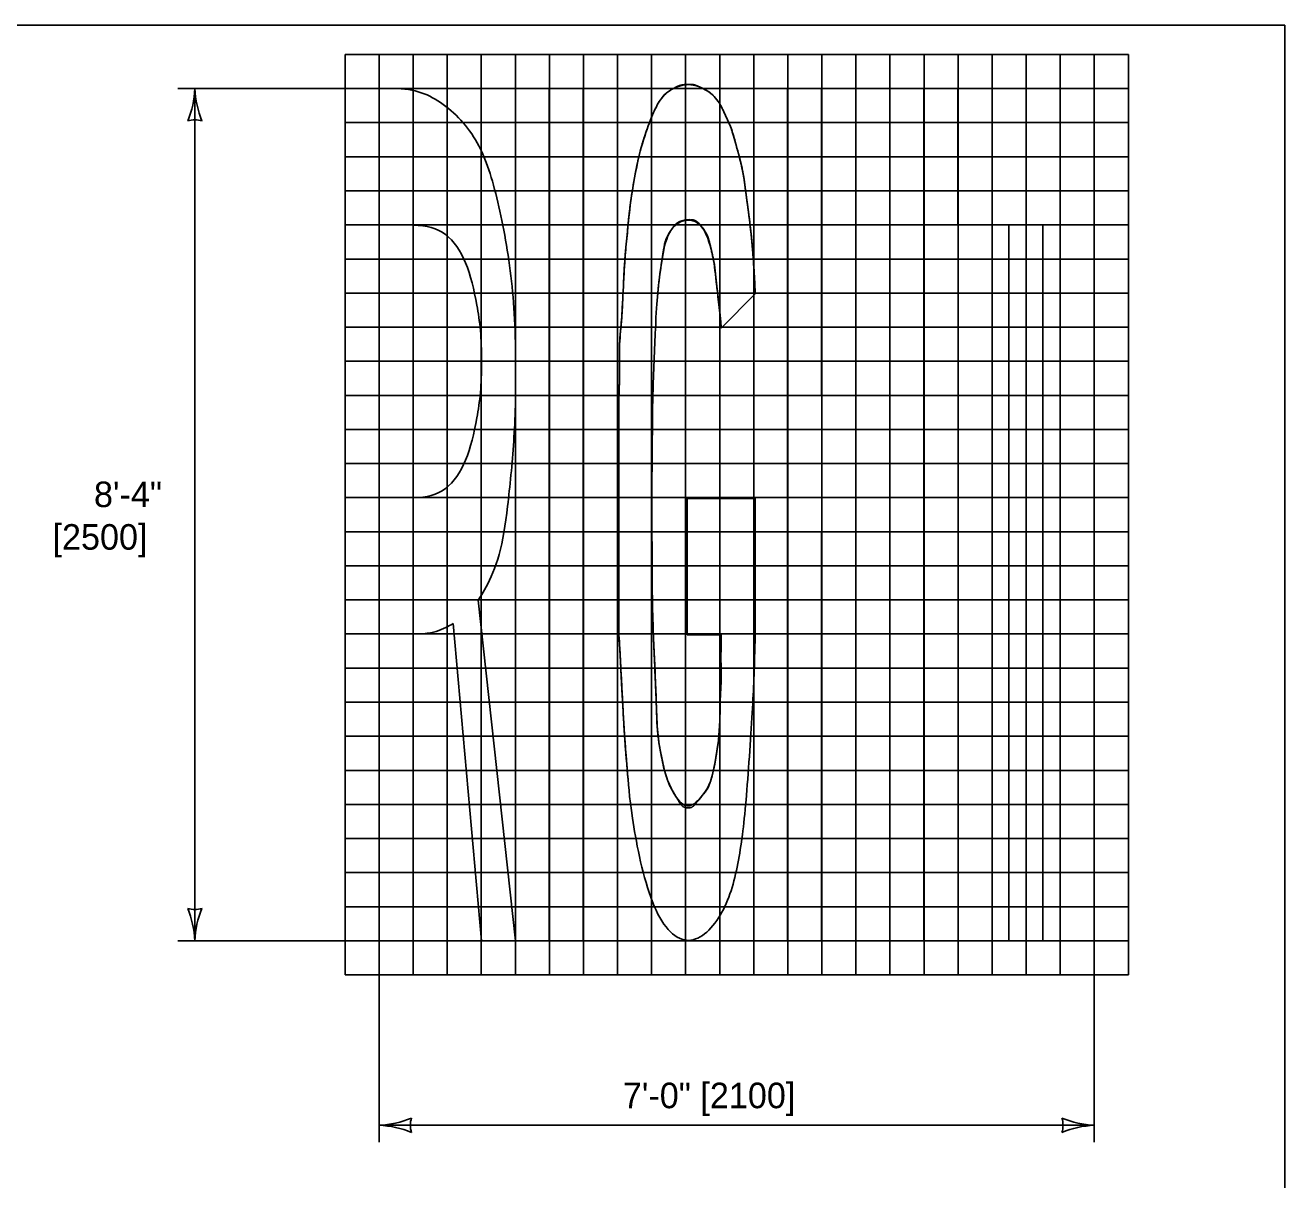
# Model space of a CAD drawing. Extents: x 49991.4 to 50021, y 49987.6 to 50011.4.
# Drawn here: x 50005.656 to 50008.615, y 50008.552 to 50011.263 of the extents above; entities that cross this region are included whole.
import ezdxf

# ---------------------------------------------------------------- set-up
doc = ezdxf.new("R2010")
doc.units = 0
for name, color, linetype in [('Level 1', 7, 'Continuous'), ('Level 2', 7, 'Continuous'), ('Level 3', 7, 'Continuous'), ('Level 9', 7, 'Continuous')]:
    doc.layers.add(name, color=color, linetype=linetype)

msp = doc.modelspace()

# ---------------------------------------------------------------- linework, layer by layer
at = {"layer": 'Level 1'}
for p, q in [((50006.4876, 50009.1134), (50006.4876, 50011.1132)), ((50006.4876, 50009.1134), (50006.4876, 50011.1132)), ((50006.4876, 50009.1134), (50006.4876, 50011.1132)), ((50006.9669, 50011.1142), (50006.887, 50011.1142)), ((50006.887, 50011.1142), (50006.887, 50009.1133)), ((50006.9669, 50009.1133), (50006.9669, 50011.1142)), ((50007.5267, 50011.1142), (50007.4468, 50011.1142)), ((50007.4468, 50011.1142), (50007.4468, 50009.1133)), ((50007.5267, 50011.1142), (50007.4468, 50011.1142)), ((50007.4468, 50011.1142), (50007.4468, 50009.1133)), ((50007.5267, 50010.3938), (50007.5267, 50011.1142)), ((50007.5267, 50010.3938), (50007.5267, 50011.1142)), ((50007.7668, 50011.1142), (50007.6868, 50011.1142)), ((50007.6868, 50011.1142), (50007.6868, 50010.3938)), ((50007.7668, 50011.1142), (50007.6868, 50011.1142)), ((50007.6868, 50011.1142), (50007.6868, 50010.3938)), ((50007.7668, 50009.1133), (50007.7668, 50011.1142)), ((50007.7668, 50009.1133), (50007.7668, 50011.1142)), ((50008.1667, 50011.1142), (50007.8467, 50011.1142)), ((50007.8467, 50011.1142), (50007.8467, 50010.7939)), ((50008.1667, 50010.7939), (50008.1667, 50011.1142)), ((50006.5676, 50010.1533), (50006.5676, 50010.7932)), ((50006.5676, 50010.7932), (50006.5676, 50010.1533)), ((50006.5676, 50010.7932), (50006.5676, 50010.1533)), ((50007.8467, 50010.7939), (50007.9667, 50010.7939)), ((50007.9667, 50010.7939), (50007.9667, 50009.1133)), ((50008.0467, 50009.1133), (50008.0467, 50010.7939)), ((50008.0467, 50010.7939), (50008.1667, 50010.7939)), ((50007.291, 50010.5518), (50007.371, 50010.6318)), ((50007.291, 50010.5518), (50007.371, 50010.6318)), ((50007.0509, 50010.3917), (50007.0509, 50009.8316)), ((50007.0509, 50010.3917), (50007.0509, 50009.8316)), ((50007.6868, 50010.3938), (50007.5267, 50010.3938)), ((50007.6868, 50010.3938), (50007.5267, 50010.3938)), ((50007.2109, 50010.1517), (50007.371, 50010.1517)), ((50007.2109, 50010.1517), (50007.2109, 50009.8316)), ((50007.371, 50010.1517), (50007.2109, 50010.1517)), ((50007.2109, 50010.1517), (50007.2109, 50009.8316)), ((50007.371, 50010.1517), (50007.371, 50009.8316)), ((50007.371, 50009.8316), (50007.371, 50010.1517)), ((50007.5267, 50009.1133), (50007.5267, 50010.0738)), ((50007.5267, 50009.1133), (50007.5267, 50010.0738)), ((50007.5273, 50010.0737), (50007.6867, 50010.0737)), ((50007.5274, 50010.0738), (50007.6874, 50010.0738)), ((50007.6868, 50010.0738), (50007.6868, 50009.1133)), ((50007.6868, 50010.0738), (50007.6868, 50009.1133)), ((50006.7202, 50009.9133), (50006.8077, 50009.1134)), ((50006.7202, 50009.9133), (50006.8077, 50009.1134)), ((50006.7202, 50009.9133), (50006.8077, 50009.1134)), ((50006.7277, 50009.1134), (50006.6618, 50009.8584)), ((50006.7277, 50009.1134), (50006.6618, 50009.8584)), ((50006.7277, 50009.1134), (50006.6618, 50009.8584)), ((50006.5676, 50009.8333), (50006.5676, 50009.1134)), ((50006.5676, 50009.8333), (50006.5676, 50009.1134)), ((50006.5676, 50009.8333), (50006.5676, 50009.1134)), ((50007.2109, 50009.8316), (50007.291, 50009.8316)), ((50007.2109, 50009.8316), (50007.291, 50009.8316)), ((50006.5676, 50009.1134), (50006.4876, 50009.1134)), ((50006.5676, 50009.1134), (50006.4876, 50009.1134)), ((50006.5676, 50009.1134), (50006.4876, 50009.1134)), ((50006.8077, 50009.1134), (50006.7277, 50009.1134)), ((50006.8077, 50009.1134), (50006.7277, 50009.1134)), ((50006.8077, 50009.1134), (50006.7277, 50009.1134)), ((50006.887, 50009.1133), (50006.9669, 50009.1133)), ((50007.4468, 50009.1133), (50007.5267, 50009.1133)), ((50007.4468, 50009.1133), (50007.5267, 50009.1133)), ((50007.6868, 50009.1133), (50007.7668, 50009.1133)), ((50007.6868, 50009.1133), (50007.7668, 50009.1133)), ((50007.9667, 50009.1133), (50008.0467, 50009.1133))]:
    msp.add_line(p, q, dxfattribs=at)
msp.add_lwpolyline([(50008.6146, 50011.2628), (50000.3356, 50011.2628), (50000.3356, 50000.0624), (50008.6146, 50000.0624)], close=True, dxfattribs=at)
for points, degree in [([(50006.4876, 50011.1132), (50006.5505, 50011.1179), (50006.6207, 50011.1), (50006.7184, 50011.007), (50006.7627, 50010.8775), (50006.7992, 50010.6887), (50006.8086, 50010.5541), (50006.8077, 50010.4733)], 3), ([(50006.4876, 50011.1132), (50006.5505, 50011.1179), (50006.6207, 50011.1), (50006.7184, 50011.007), (50006.7627, 50010.8775), (50006.7992, 50010.6887), (50006.8086, 50010.5541), (50006.8077, 50010.4733)], 3), ([(50006.4876, 50011.1132), (50006.5505, 50011.1179), (50006.6207, 50011.1), (50006.7184, 50011.007), (50006.7627, 50010.8775), (50006.7992, 50010.6887), (50006.8086, 50010.5541), (50006.8077, 50010.4733)], 3), ([(50007.0509, 50010.3917), (50007.0516, 50010.4147), (50007.0529, 50010.4527), (50007.051, 50010.5134), (50007.0579, 50010.5737), (50007.0609, 50010.6473), (50007.0654, 50010.7285), (50007.0703, 50010.7702), (50007.0765, 50010.8407), (50007.0866, 50010.9025), (50007.1014, 50010.9763), (50007.1269, 50011.0469), (50007.142, 50011.08), (50007.1645, 50011.11), (50007.2106, 50011.1281), (50007.2501, 50011.116), (50007.2839, 50011.0901), (50007.3005, 50011.0511), (50007.3147, 50011.0229), (50007.3251, 50010.9839), (50007.3417, 50010.9253), (50007.3476, 50010.8779), (50007.3575, 50010.8075), (50007.3649, 50010.7392), (50007.3686, 50010.6785), (50007.3704, 50010.6439), (50007.371, 50010.6318)], 3), ([(50007.1741, 50011.1116), (50007.1585, 50011.1021), (50007.1496, 50011.0901), (50007.1425, 50011.0782)], 2), ([(50007.2112, 50011.1238), (50007.1981, 50011.1232), (50007.1846, 50011.1179), (50007.1741, 50011.1116)], 2), ([(50007.2459, 50011.1154), (50007.2351, 50011.1206), (50007.2233, 50011.1243), (50007.2112, 50011.1238)], 2), ([(50007.2805, 50011.0881), (50007.2715, 50011.0996), (50007.2595, 50011.1088), (50007.2459, 50011.1154)], 2), ([(50007.3018, 50011.0493), (50007.2959, 50011.0619), (50007.2898, 50011.0762), (50007.2805, 50011.0881)], 2), ([(50007.1425, 50011.0782), (50007.1365, 50011.0681), (50007.1319, 50011.0579), (50007.1259, 50011.0427)], 2), ([(50007.1259, 50011.0427), (50007.1194, 50011.0262), (50007.1113, 50011.0037), (50007.1052, 50010.983)], 2), ([(50007.3238, 50010.9889), (50007.3206, 50011.0008), (50007.3147, 50011.0229), (50007.3062, 50011.0397), (50007.3018, 50011.0492)], 3), ([(50007.1051, 50010.983), (50007.0977, 50010.9578), (50007.0866, 50010.9025), (50007.0788, 50010.8553), (50007.0753, 50010.8236)], 3), ([(50007.3389, 50010.9314), (50007.3349, 50010.9493), (50007.3289, 50010.9704), (50007.3238, 50010.9889)], 2), ([(50007.3481, 50010.8751), (50007.3456, 50010.8942), (50007.3435, 50010.9108), (50007.3389, 50010.9314)], 2), ([(50007.3562, 50010.8149), (50007.3536, 50010.8354), (50007.3506, 50010.8564), (50007.3481, 50010.8751)], 2), ([(50007.0753, 50010.8235), (50007.0735, 50010.807), (50007.0719, 50010.7894), (50007.0704, 50010.7743)], 2), ([(50007.3646, 50010.7356), (50007.3624, 50010.7617), (50007.3596, 50010.7878), (50007.3562, 50010.8149)], 2), ([(50006.5676, 50010.7932), (50006.5998, 50010.7931), (50006.6474, 50010.7796), (50006.6942, 50010.71), (50006.7188, 50010.6085), (50006.729, 50010.528), (50006.7277, 50010.4733)], 3), ([(50006.7277, 50010.4733), (50006.729, 50010.528), (50006.7188, 50010.6085), (50006.6942, 50010.71), (50006.6474, 50010.7796), (50006.5998, 50010.7931), (50006.5676, 50010.7932)], 3), ([(50006.7277, 50010.4733), (50006.729, 50010.528), (50006.7188, 50010.6085), (50006.6942, 50010.71), (50006.6474, 50010.7796), (50006.5998, 50010.7931), (50006.5676, 50010.7932)], 3), ([(50007.291, 50010.5518), (50007.2891, 50010.5788), (50007.2789, 50010.6613), (50007.2741, 50010.7148), (50007.2519, 50010.7954), (50007.208, 50010.813), (50007.1642, 50010.7821), (50007.1506, 50010.709), (50007.1409, 50010.6302), (50007.137, 50010.5709), (50007.1294, 50010.3786), (50007.1295, 50010.3001), (50007.1269, 50010.095), (50007.1294, 50010.0223), (50007.1284, 50009.8953), (50007.1353, 50009.7502), (50007.1389, 50009.6675), (50007.1405, 50009.6001), (50007.1503, 50009.5469), (50007.1591, 50009.5047), (50007.1739, 50009.467), (50007.2101, 50009.4124), (50007.2555, 50009.4624), (50007.2702, 50009.4946), (50007.2821, 50009.5651), (50007.286, 50009.5936), (50007.2886, 50009.6496), (50007.2883, 50009.6708), (50007.2896, 50009.7032), (50007.2921, 50009.7406), (50007.2896, 50009.7667), (50007.2908, 50009.7991), (50007.291, 50009.8316)], 3), ([(50007.1734, 50010.7819), (50007.182, 50010.7947), (50007.1942, 50010.8033), (50007.2069, 50010.8053)], 2), ([(50007.2069, 50010.8053), (50007.2215, 50010.8076), (50007.2369, 50010.8014), (50007.2477, 50010.7868)], 2), ([(50007.2477, 50010.7868), (50007.2582, 50010.7725), (50007.2644, 50010.7501), (50007.2685, 50010.7319)], 2), ([(50007.0704, 50010.7743), (50007.0688, 50010.7578), (50007.0672, 50010.7442), (50007.0658, 50010.727)], 2), ([(50007.1515, 50010.7097), (50007.1554, 50010.7347), (50007.1606, 50010.7629), (50007.1734, 50010.7819)], 2), ([(50007.0658, 50010.727), (50007.0642, 50010.7069), (50007.0609, 50010.6473), (50007.0588, 50010.5971), (50007.0567, 50010.5699)], 3), ([(50007.2685, 50010.7319), (50007.2751, 50010.7033), (50007.2768, 50010.685), (50007.2796, 50010.6592)], 2), ([(50007.3691, 50010.668), (50007.3679, 50010.6905), (50007.3665, 50010.7131), (50007.3646, 50010.7356)], 2), ([(50007.1289, 50010.2692), (50007.1295, 50010.3296), (50007.1294, 50010.3786), (50007.137, 50010.5709), (50007.1409, 50010.6302), (50007.1479, 50010.6869), (50007.1515, 50010.7097)], 3), ([(50007.371, 50010.6318), (50007.3704, 50010.6439), (50007.3698, 50010.6559), (50007.3691, 50010.668)], 2), ([(50007.2796, 50010.6592), (50007.2834, 50010.6255), (50007.2891, 50010.5788), (50007.291, 50010.5518)], 2), ([(50007.0567, 50010.5699), (50007.0549, 50010.5479), (50007.0526, 50010.5272), (50007.0521, 50010.5053)], 2), ([(50007.0521, 50010.5053), (50007.0517, 50010.4907), (50007.0522, 50010.4757), (50007.0523, 50010.4607)], 2), ([(50006.7277, 50010.4733), (50006.729, 50010.4185), (50006.7188, 50010.338), (50006.6942, 50010.2365), (50006.6474, 50010.1669), (50006.5998, 50010.1534), (50006.5676, 50010.1533)], 3), ([(50006.5676, 50010.1533), (50006.5998, 50010.1534), (50006.6474, 50010.1669), (50006.6942, 50010.2365), (50006.7188, 50010.338), (50006.729, 50010.4185), (50006.7277, 50010.4733)], 3), ([(50006.5676, 50010.1533), (50006.5998, 50010.1534), (50006.6474, 50010.1669), (50006.6942, 50010.2365), (50006.7188, 50010.338), (50006.729, 50010.4185), (50006.7277, 50010.4733)], 3), ([(50006.8077, 50010.4733), (50006.809, 50010.393), (50006.8055, 50010.2861), (50006.7894, 50010.1258), (50006.7726, 50010.0148), (50006.7377, 50009.9375), (50006.7202, 50009.9133), (50006.7202, 50009.9133)], 3), ([(50006.8077, 50010.4733), (50006.809, 50010.393), (50006.8055, 50010.2861), (50006.7894, 50010.1258), (50006.7726, 50010.0148), (50006.7377, 50009.9375), (50006.7202, 50009.9133), (50006.7202, 50009.9133)], 3), ([(50006.8077, 50010.4733), (50006.809, 50010.393), (50006.8055, 50010.2861), (50006.7894, 50010.1258), (50006.7726, 50010.0148), (50006.7377, 50009.9375), (50006.7202, 50009.9133), (50006.7202, 50009.9133)], 3), ([(50007.0523, 50010.4607), (50007.0524, 50010.4377), (50007.0516, 50010.4147), (50007.0509, 50010.3917)], 2), ([(50007.1278, 50010.0983), (50007.1275, 50010.1457), (50007.1284, 50010.2171), (50007.1289, 50010.2692)], 2), ([(50007.1289, 50010.0132), (50007.1287, 50010.0429), (50007.128, 50010.0646), (50007.1278, 50010.0982)], 2), ([(50007.1295, 50009.9098), (50007.1288, 50009.949), (50007.1291, 50009.9848), (50007.1289, 50010.0132)], 2), ([(50007.1388, 50009.6637), (50007.1381, 50009.6864), (50007.1353, 50009.7502), (50007.1305, 50009.8509), (50007.1295, 50009.9098)], 3), ([(50006.6618, 50009.8584), (50006.6618, 50009.8584), (50006.6341, 50009.8417), (50006.603, 50009.8338), (50006.5676, 50009.8333)], 3), ([(50006.6618, 50009.8584), (50006.6618, 50009.8584), (50006.6341, 50009.8417), (50006.603, 50009.8338), (50006.5676, 50009.8333)], 3), ([(50006.6618, 50009.8584), (50006.6618, 50009.8584), (50006.6341, 50009.8417), (50006.603, 50009.8338), (50006.5676, 50009.8333)], 3), ([(50007.0509, 50009.8316), (50007.0578, 50009.7076), (50007.0632, 50009.5959), (50007.0711, 50009.5081), (50007.0791, 50009.4017), (50007.127, 50009.1703), (50007.2147, 50009.0857), (50007.3014, 50009.1734), (50007.3344, 50009.3019), (50007.3503, 50009.4363), (50007.3663, 50009.6837), (50007.3689, 50009.7529), (50007.371, 50009.8316)], 3), ([(50007.0509, 50009.8316), (50007.0578, 50009.7076), (50007.0609, 50009.6445), (50007.0639, 50009.598)], 2), ([(50007.0639, 50009.5979), (50007.0662, 50009.5621), (50007.0711, 50009.5081), (50007.0791, 50009.4017), (50007.127, 50009.1703), (50007.2147, 50009.0857), (50007.3014, 50009.1734), (50007.3344, 50009.3019), (50007.3503, 50009.4363), (50007.3663, 50009.6837), (50007.3689, 50009.7529), (50007.371, 50009.8316)], 3), ([(50007.291, 50009.8316), (50007.2908, 50009.7991), (50007.2903, 50009.7863), (50007.2903, 50009.7763)], 2), ([(50007.2903, 50009.7763), (50007.2901, 50009.761), (50007.2921, 50009.7406), (50007.2904, 50009.7154), (50007.2897, 50009.7031)], 3), ([(50007.2897, 50009.7031), (50007.2892, 50009.6928), (50007.2888, 50009.684), (50007.2887, 50009.6764)], 2), ([(50007.1419, 50009.6027), (50007.1399, 50009.6228), (50007.1394, 50009.6437), (50007.1388, 50009.6637)], 2), ([(50007.2887, 50009.6764), (50007.2884, 50009.6648), (50007.2885, 50009.6557), (50007.2879, 50009.6385)], 2), ([(50007.2879, 50009.6385), (50007.2876, 50009.6272), (50007.2869, 50009.6123), (50007.286, 50009.6002)], 2), ([(50007.152, 50009.5394), (50007.1479, 50009.5601), (50007.144, 50009.5809), (50007.1419, 50009.6027)], 2), ([(50007.286, 50009.6002), (50007.2849, 50009.5851), (50007.2834, 50009.5745), (50007.2804, 50009.556)], 2), ([(50007.2804, 50009.556), (50007.2778, 50009.5397), (50007.2741, 50009.5173), (50007.2691, 50009.4994)], 2), ([(50007.1626, 50009.4973), (50007.1573, 50009.5133), (50007.1546, 50009.5263), (50007.152, 50009.5394)], 2), ([(50007.1826, 50009.4552), (50007.1708, 50009.4749), (50007.1662, 50009.4867), (50007.1626, 50009.4973)], 2), ([(50007.2691, 50009.4994), (50007.2641, 50009.4811), (50007.2579, 50009.4675), (50007.2382, 50009.4441)], 2), ([(50007.2128, 50009.4253), (50007.2014, 50009.4255), (50007.1904, 50009.4421), (50007.1826, 50009.4552)], 2), ([(50007.2382, 50009.4441), (50007.2309, 50009.4353), (50007.2218, 50009.4252), (50007.2128, 50009.4253)], 2)]:
    msp.add_open_spline(points, degree=degree, dxfattribs=at)
at = {"layer": 'Level 3'}
for p, q in [((50006.4476, 50011.114), (50006.0148, 50011.114)), ((50006.0548, 50011.114), (50006.0548, 50009.1134)), ((50008.1672, 50010.7539), (50008.1672, 50008.6403)), ((50006.4476, 50009.1134), (50006.0148, 50009.1134)), ((50006.4876, 50009.0734), (50006.4876, 50008.6403)), ((50006.4876, 50008.6803), (50008.1672, 50008.6803))]:
    msp.add_line(p, q, dxfattribs=at)
for centre, radius, start, end in [((50005.8327, 50011.1232), 0.2223, 337.456, 357.6395), ((50006.2875, 50011.1255), 0.233, 182.8273, 202.0772), ((50006.0548, 50010.9858), 0.0548, 72.1388, 107.8612), ((50006.0548, 50009.2416), 0.0548, 252.1388, 287.8612), ((50005.8221, 50009.1019), 0.233, 2.8273, 22.0772), ((50006.2769, 50009.1042), 0.2223, 157.456, 177.6395), ((50006.4785, 50008.9024), 0.2223, 272.3605, 292.544), ((50006.6158, 50008.6803), 0.0548, 162.1388, 197.8612), ((50008.1764, 50008.9024), 0.2223, 247.456, 267.6395), ((50008.039, 50008.6803), 0.0548, 342.1388, 17.8612), ((50006.4761, 50008.4476), 0.233, 67.9228, 87.1727), ((50008.1787, 50008.4476), 0.233, 92.8273, 112.0772)]:
    msp.add_arc(centre, radius, start, end, dxfattribs=at)
at = {"layer": 'Level 9'}
for p, q in [((50006.4076, 50011.1941), (50006.4076, 50009.0333)), ((50006.4076, 50011.1941), (50008.2472, 50011.1941)), ((50006.4876, 50011.1941), (50006.4876, 50009.0333)), ((50006.5676, 50011.1941), (50006.5676, 50009.0333)), ((50006.6476, 50011.1941), (50006.6476, 50009.0333)), ((50006.7276, 50011.1941), (50006.7276, 50009.0333)), ((50006.8075, 50011.1941), (50006.8075, 50009.0333)), ((50006.8875, 50011.1941), (50006.8875, 50009.0333)), ((50006.9675, 50011.1941), (50006.9675, 50009.0333)), ((50007.0475, 50011.1941), (50007.0475, 50009.0333)), ((50007.1275, 50011.1941), (50007.1275, 50009.0333)), ((50007.2075, 50011.1941), (50007.2075, 50009.0333)), ((50007.2874, 50011.1941), (50007.2874, 50009.0333)), ((50007.3674, 50011.1941), (50007.3674, 50009.0333)), ((50007.4474, 50011.1941), (50007.4474, 50009.0333)), ((50007.5274, 50011.1941), (50007.5274, 50009.0333)), ((50007.6074, 50011.1941), (50007.6074, 50009.0333)), ((50007.6873, 50011.1941), (50007.6873, 50009.0333)), ((50007.7673, 50011.1941), (50007.7673, 50009.0333)), ((50007.8473, 50011.1941), (50007.8473, 50009.0333)), ((50007.9273, 50011.1941), (50007.9273, 50009.0333)), ((50008.0073, 50011.1941), (50008.0073, 50009.0333)), ((50008.0873, 50011.1941), (50008.0873, 50009.0333)), ((50008.1672, 50011.1941), (50008.1672, 50009.0333)), ((50008.2472, 50011.1941), (50008.2472, 50009.0333)), ((50006.4076, 50011.114), (50008.2472, 50011.114)), ((50006.4876, 50011.114), (50008.1672, 50011.114)), ((50006.4076, 50011.034), (50008.2472, 50011.034)), ((50006.4076, 50010.954), (50008.2472, 50010.954)), ((50006.4076, 50010.874), (50008.0073, 50010.874)), ((50006.4876, 50010.874), (50008.0073, 50010.874)), ((50006.4876, 50010.874), (50008.2472, 50010.874)), ((50006.4076, 50010.7939), (50008.0073, 50010.7939)), ((50006.4876, 50010.7939), (50008.0073, 50010.7939)), ((50006.4876, 50010.7939), (50008.2472, 50010.7939)), ((50006.4076, 50010.7139), (50008.0073, 50010.7139)), ((50006.4876, 50010.7139), (50008.2472, 50010.7139)), ((50006.4076, 50010.6339), (50008.0073, 50010.6339)), ((50006.4876, 50010.6339), (50008.2472, 50010.6339)), ((50006.4076, 50010.5539), (50008.0073, 50010.5539)), ((50006.4876, 50010.5539), (50008.2472, 50010.5539)), ((50006.4076, 50010.4738), (50008.0073, 50010.4738)), ((50006.4876, 50010.4738), (50008.2472, 50010.4738)), ((50006.4076, 50010.3938), (50008.0073, 50010.3938)), ((50006.4876, 50010.3938), (50008.2472, 50010.3938)), ((50006.4076, 50010.3138), (50008.0073, 50010.3138)), ((50006.4876, 50010.3138), (50008.2472, 50010.3138)), ((50006.4076, 50010.2337), (50008.0073, 50010.2337)), ((50006.4876, 50010.2337), (50008.2472, 50010.2337)), ((50006.4076, 50010.1537), (50008.0073, 50010.1537)), ((50006.4876, 50010.1537), (50008.2472, 50010.1537)), ((50006.4076, 50010.0737), (50008.0073, 50010.0737)), ((50006.4876, 50010.0737), (50008.2472, 50010.0737)), ((50006.4076, 50009.9937), (50008.0073, 50009.9937)), ((50006.4876, 50009.9937), (50008.2472, 50009.9937)), ((50006.4076, 50009.9136), (50008.0073, 50009.9136)), ((50006.4876, 50009.9136), (50008.2472, 50009.9136)), ((50006.4076, 50009.8336), (50008.0073, 50009.8336)), ((50006.4876, 50009.8336), (50008.2472, 50009.8336)), ((50006.4076, 50009.7536), (50008.0073, 50009.7536)), ((50006.4876, 50009.7536), (50008.2472, 50009.7536)), ((50006.4076, 50009.6736), (50008.0073, 50009.6736)), ((50006.4876, 50009.6736), (50008.2472, 50009.6736)), ((50006.4076, 50009.5935), (50008.0073, 50009.5935)), ((50006.4876, 50009.5935), (50008.2472, 50009.5935)), ((50006.4076, 50009.5135), (50008.0073, 50009.5135)), ((50006.4876, 50009.5135), (50008.2472, 50009.5135)), ((50006.4076, 50009.4335), (50008.0073, 50009.4335)), ((50006.4876, 50009.4335), (50008.2472, 50009.4335)), ((50006.4076, 50009.3534), (50008.0073, 50009.3534)), ((50006.4876, 50009.3534), (50008.2472, 50009.3534)), ((50006.4076, 50009.2734), (50008.0073, 50009.2734)), ((50006.4876, 50009.2734), (50008.2472, 50009.2734)), ((50006.4076, 50009.1934), (50008.0073, 50009.1934)), ((50006.4876, 50009.1934), (50008.2472, 50009.1934)), ((50006.4076, 50009.1134), (50008.0073, 50009.1134)), ((50006.4876, 50009.1134), (50008.2472, 50009.1134)), ((50006.4076, 50009.0333), (50008.2472, 50009.0333))]:
    msp.add_line(p, q, dxfattribs=at)

# ---------------------------------------------------------------- texts
at = {"layer": 'Level 2'}
for s, p in [('8\'-4"', (50005.8179, 50010.1315)), ('[2500]', (50005.7205, 50010.0315)), ('7\'-0" [2100]', (50007.06, 50008.7203))]:
    msp.add_text(s, height=0.06, dxfattribs=at).set_placement(p)

doc.saveas('drawing.dxf')
